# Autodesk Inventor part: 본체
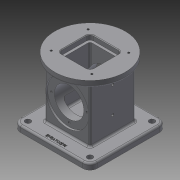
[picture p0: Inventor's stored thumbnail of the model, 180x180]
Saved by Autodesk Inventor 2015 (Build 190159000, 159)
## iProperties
Created: 2021-05
Part Number: 본체
Material: 일반
Document SubType Name: Modeling
Designer: 1019876
Density: 1 g/cm^3
Appearance: 기본값
Author: 1019876
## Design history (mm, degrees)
sketch "스케치1"
  geometry: L1 (-62.5, -62.5)-(62.5, -62.5); L2 (62.5, -62.5)-(62.5, 62.5); L3 (62.5, 62.5)-(-62.5, 62.5); L4 (-62.5, 62.5)-(-62.5, -62.5); L5 (-62.5, -62.5)-(62.5, 62.5); L6 (62.5, -62.5)-(-62.5, 62.5); 1 further point
  constraints: 12 end point, 2 midpoint, 2 parallel, 1 horizontal, 1 perpendicular
  dimensions: "d0" = 125 distance of L3.end L2.end; "d1" = 125 distance of L2.end L1.end
extrude "돌출1" new body sketch "스케치1" distance "d2" = 10; taper "d3" = 0 deg
sketch "스케치2"
  geometry: L1 (37, -37)-(-37, -37); L2 (-37, -37)-(-37, 37); L3 (-37, 37)-(37, 37); L4 (37, 37)-(37, -37); L5 (37, -37)-(-37, 37); L6 (-37, -37)-(37, 37); 1 further point
  constraints: 12 end point, 2 midpoint, 2 parallel, 1 horizontal, 1 perpendicular
  dimensions: "d4" = 74 distance of L2.end L3.end; "d5" = 74 distance of L1.end L2.end
extrude "돌출2" join sketch "스케치2" distance "d6" = 88; taper "d7" = 0 deg
sketch "스케치3"
  geometry: C1 r 57.5 at (0, 0); 1 further point
  constraints: 1 centre point, 1 coincident
  dimensions: "d8" = 57.5 radius of C1
extrude "돌출3" join sketch "스케치3" distance "d9" = 10; taper "d10" = 0 deg
sketch "스케치4"
  geometry: L1 (-26, -26)-(26, -26); L2 (26, -26)-(26, 26); L3 (26, 26)-(-26, 26); L4 (-26, 26)-(-26, -26); L5 (-26, -26)-(26, 26); L6 (26, -26)-(-26, 26); C1 r 57.5 at (0, 0) reference
  constraints: 12 end point, 2 midpoint, 2 parallel, 1 horizontal, 1 perpendicular
  dimensions: "d11" = 52 distance of L3.end L2.end; "d12" = 52 distance of L2.end L1.end
extrude "돌출4" cut sketch "스케치4" distance "d13" = 8; taper "d14" = 0 deg
sketch "스케치5"
  geometry: L1 (-25.5, -10)-(99.5, -10) reference; C1 r 35 at (37, 44); 2 further points
  constraints: 1 centre point, 1 midpoint, 1 vertical alignment
  dimensions: "d15" = 35 radius of C1; "d16" = 54 distance from line of L1 C1.centre
extrude "돌출5" cut sketch "스케치5" distance "d17" = 3; taper "d18" = 0 deg
sketch "스케치6"
  geometry: C1 r 35 at (0, 0) reference; 1 further point
hole "구멍1" sketch "스케치6" at (0, 0) diameter "d19" = 48; stored, may be unused: countersink angle "d23" = 90 deg, drill point angle "d25" = 118 deg; dims "d20" = 6, "d21" = 4, "d22" = 2, "d24" = 8
sketch "스케치7"
  geometry: L1 (0, 0)-(0, 29); C1 r 35 at (0, 0) reference; 1 further point
  constraints: 2 end point, 1 vertical
  dimensions: "d26" = 29 distance of L1.start L1.end
hole "구멍2" sketch "스케치7" at (0, 29) diameter "d27" = 3.242; stored, may be unused: countersink angle "d31" = 90 deg, drill point angle "d33" = 118 deg; dims "d28" = 8, "d29" = 4, "d30" = 2, "d32" = 10
sketch "스케치8"
  geometry: C1 r 28 at (0, 0); 1 further point
  constraints: 1 centre point, 1 coincident
  dimensions: "d37" = 28 radius of C1
extrude "돌출6" cut sketch "스케치8" distance "d38" = 18; taper "d39" = -10 deg
sketch "스케치9"
  geometry: L1 (-22, -22)-(22, -22); L2 (22, -22)-(22, 22); L3 (22, 22)-(-22, 22); L4 (-22, 22)-(-22, -22); L5 (-22, -22)-(22, 22); L6 (22, -22)-(-22, 22); 1 further point
  constraints: 12 end point, 2 midpoint, 2 parallel, 1 horizontal, 1 perpendicular
  dimensions: "d40" = 44 distance of L3.end L2.end; "d41" = 44 distance of L2.end L1.end
extrude "돌출7" cut sketch "스케치9" distance "d42" = 74; taper "d43" = 0 deg
fillet "모깎기1" dims "d44" = 12
hole "구멍3" diameter "d47" = 9; stored, may be unused: countersink angle "d51" = 90 deg, drill point angle "d53" = 118 deg; dims "d45" = 10, "d46" = 10, "d48" = 8, "d49" = 4, "d50" = 2, "d52" = 10
hole "구멍4" diameter "d56" = 9; stored, may be unused: countersink angle "d60" = 90 deg, drill point angle "d62" = 118 deg; dims "d54" = 10, "d55" = 10, "d57" = 8, "d58" = 4, "d59" = 2, "d61" = 10
hole "구멍5" diameter "d65" = 9; stored, may be unused: countersink angle "d69" = 90 deg, drill point angle "d71" = 118 deg; dims "d63" = 10, "d64" = 10, "d66" = 8, "d67" = 4, "d68" = 2, "d70" = 10
hole "구멍6" diameter "d74" = 9; stored, may be unused: countersink angle "d78" = 90 deg, drill point angle "d80" = 118 deg; dims "d72" = 10, "d73" = 10, "d75" = 8, "d76" = 4, "d77" = 2, "d79" = 10
sketch "스케치10"
  geometry: C1 r 57.5 at (0, 0) reference; 4 further points
  constraints: 2 horizontal alignment, 2 vertical alignment
  dimensions: "d81" = 60 distance of point (33, -30) point (33, 30); "d82" = 30 vertical distance of C1.centre point (33, 30); "d83" = 66 distance of point (33, 30) point (-33, 30); "d84" = 33 horizontal distance of C1.centre point (-33, 30)
hole "구멍7" sketch "스케치10" at (-33, 30), (33, 30), (-33, -30), (33, -30) diameter "d85" = 3.242; stored, may be unused: countersink angle "d89" = 90 deg, drill point angle "d91" = 118 deg; dims "d86" = 8, "d87" = 4, "d88" = 2, "d90" = 10
sketch "스케치11"
  geometry: L1 (10, -13.5)-(10, 87.5) reference; 4 further points
  constraints: 2 horizontal alignment, 1 midpoint
  dimensions: "d92" = 43 distance of point (-27, 37) point (-70, 37); "d93" = 37 distance from line of L1 point (-27, 37)
hole "구멍8" sketch "스케치11" at (-70, 37), (-27, 37) diameter "d94" = 4.134; stored, may be unused: countersink angle "d98" = 90 deg, drill point angle "d100" = 118 deg; dims "d95" = 10, "d96" = 4, "d97" = 2, "d99" = 20
fillet "모깎기2" dims "d101" = 6
fillet "모깎기3" dims "d102" = 3
fillet "모깎기4" dims "d103" = 3
fillet "모깎기5" dims "d104" = 3
fillet "모깎기6" dims "d105" = 3
fillet "모깎기7" dims "d106" = 3
chamfer "모따기1" distance "d107" = 1; stored, may be unused: second distance "d108" = 2, angle "d109" = 45 deg
sketch "스케치12"
  geometry: 2 further points
  constraints: 1 vertical alignment, 1 other
  dimensions: "d110" = 55 distance of point (0, 0) point (0, -55)
feature "엠보싱1" sketch "스케치12" dims "d0" = 125, "d1" = 125, "d111" = 0.5, "d112" = 0
node "솔리드1"
mirror "대칭1"
pattern_circular "원형 패턴1" dims angle "d35" = 360 deg
mirror "대칭2"
